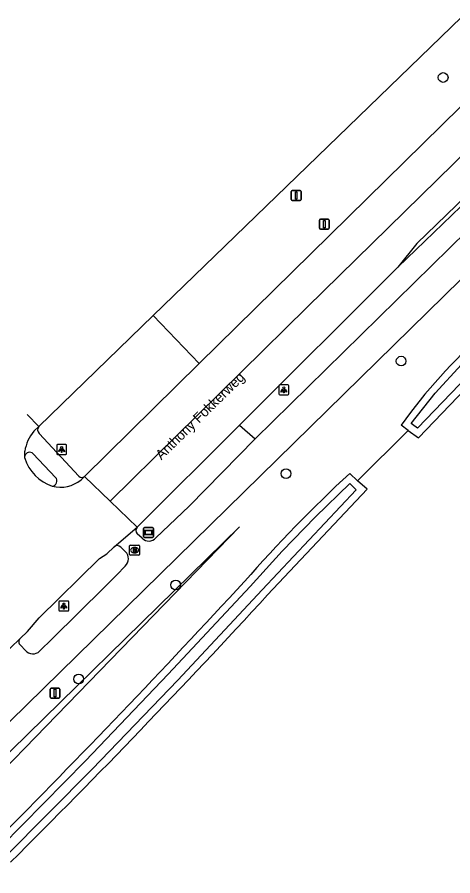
# Model space of a CAD drawing. Extents: x 156502 to 159074, y 384229 to 386094.
# Drawn here: x 156893 to 156936.7, y 385875.5 to 385961.8 of the extents above; entities that cross this region are included whole.
import ezdxf

# ---------------------------------------------------------------- set-up
doc = ezdxf.new("R2010")
doc.units = 0
for name, color, linetype in [('IMGEO_Berm_groen', 7, 'Continuous'), ('IMGEO_Boom', 7, 'Continuous'), ('IMGEO_Brandkraan', 7, 'Continuous'), ('IMGEO_Duiker', 7, 'Continuous'), ('IMGEO_Fietspad_gesloten', 7, 'Continuous'), ('IMGEO_Fietspad_open', 7, 'Continuous'), ('IMGEO_Lichtpunt', 7, 'Continuous'), ('IMGEO_Loofbos', 7, 'Continuous'), ('IMGEO_Openbare_ruimte_label', 7, 'Continuous'), ('IMGEO_OVBaan_gesloten', 7, 'Continuous'), ('IMGEO_Rijbaan_regionaal_gesloten', 7, 'Continuous'), ('IMGEO_Verkeersbordpaal', 7, 'Continuous'), ('IMGEO_Verkeerseiland_open', 7, 'Continuous'), ('IMGEO_Verklikker', 7, 'Continuous'), ('IMGEO_Waterloop', 7, 'Continuous')]:
    doc.layers.add(name, color=color, linetype=linetype)

msp = doc.modelspace()

# ---------------------------------------------------------------- linework, layer by layer
at = {"layer": 'IMGEO_Berm_groen'}
msp.add_lwpolyline([(156915.286, 385920.806), (156916.861, 385919.427)], dxfattribs=at)
at = {"layer": 'IMGEO_Boom'}
for centre in [(156935.717, 385955.717), (156931.498, 385927.235), (156919.949, 385915.936), (156908.883, 385904.761), (156899.148, 385895.304)]:
    msp.add_circle(centre, 0.489, dxfattribs=at)
at = {"layer": 'IMGEO_Brandkraan'}
for p, q in [((156904.254, 385907.821), (156904.254, 385908.673)), ((156904.329, 385908.747), (156905.181, 385908.747)), ((156904.742, 385908.527), (156904.767, 385908.527)), ((156905.255, 385908.673), (156905.255, 385907.821)), ((156905.181, 385907.747), (156904.329, 385907.747)), ((156904.765, 385907.967), (156904.74, 385907.967))]:
    msp.add_line(p, q, dxfattribs=at)
for points in [[(156904.254, 385907.821), (156904.254, 385908.673)], [(156904.329, 385908.747), (156905.181, 385908.747)], [(156904.602, 385908.447), (156904.602, 385908.047), (156904.815, 385908.047)], [(156904.833, 385908.447), (156904.602, 385908.447)], [(156904.781, 385908.366), (156904.727, 385908.366), (156904.727, 385908.29)], [(156905.255, 385908.673), (156905.255, 385907.821)], [(156905.181, 385907.747), (156904.329, 385907.747)], [(156904.727, 385908.29), (156904.78, 385908.29)], [(156904.789, 385908.214), (156904.727, 385908.214), (156904.727, 385908.133)], [(156904.727, 385908.133), (156904.789, 385908.133)]]:
    msp.add_lwpolyline(points, dxfattribs=at)
for centre, radius, start, end in [((156904.331, 385908.671), 0.0765, 91.55205, 178.44795), ((156904.331, 385908.671), 0.0765, 91.55205, 178.44795), ((156904.782, 385908.328), 0.0379, 267.82845, 90.93552), ((156904.837, 385908.302), 0.145, 59.4692, 91.53667), ((156904.862, 385908.349), 0.0922, 285.51372, 58.15012), ((156905.179, 385908.671), 0.0765, 1.55205, 88.44795), ((156905.179, 385908.671), 0.0765, 1.55205, 88.44795), ((156904.331, 385907.823), 0.0765, 181.55205, 268.44795), ((156904.331, 385907.823), 0.0765, 181.55205, 268.44795), ((156904.79, 385908.173), 0.0404, 269.87594, 90.50774), ((156904.821, 385908.298), 0.251, 268.66757, 293.53466), ((156904.867, 385908.157), 0.105, 301.31148, 78.98903), ((156905.179, 385907.823), 0.0765, 271.55205, 358.44795), ((156905.179, 385907.823), 0.0765, 271.55205, 358.44795)]:
    msp.add_arc(centre, radius, start, end, dxfattribs=at)
for centre, major_axis, ratio, start_param, end_param in [((156904.741, 385908.247), (-0.387, 0.002), 0.722429, 4.712389, 7.853982), ((156904.766, 385908.247), (-0.39, 0.002), 0.717154, 1.570796, 4.712389)]:
    msp.add_ellipse(centre, major_axis=major_axis, ratio=ratio, start_param=start_param, end_param=end_param, dxfattribs=at)
at = {"layer": 'IMGEO_Duiker'}
msp.add_lwpolyline([(156932.218, 385920.282), (156927.135, 385915.226)], dxfattribs=at)
at = {"layer": 'IMGEO_Fietspad_gesloten'}
for points in [[(156916.861, 385919.427), (156943.436, 385945.532), (156945.978, 385947.733)], [(156947.572, 385944.991), (156944.187, 385942.001), (156873.791, 385872.985)], [(156916.861, 385919.427), (156910.242, 385912.682), (156906.88, 385909.479)], [(156905.515, 385909.453), (156905.007, 385909.901)], [(156903.357, 385908.566), (156903.843, 385908.097)], [(156903.815, 385906.653), (156902.968, 385905.759), (156901.719, 385904.522), (156896.499, 385899.38), (156895.214, 385898.109)], [(156893.799, 385898.18), (156893.291, 385898.71)]]:
    msp.add_lwpolyline(points, dxfattribs=at)
for centre, radius, start, end in [((156905.345, 385910.229), 0.471, 135.50454, 224.14716), ((156906.186, 385910.074), 0.914, 222.79377, 319.38866), ((156903.002, 385908.185), 0.52, 47.025, 127.15622), ((156903.124, 385907.389), 1.01, 313.22156, 44.55672), ((156893.595, 385899.063), 0.466, 137.59497, 229.26886), ((156894.541, 385898.827), 0.984, 221.09933, 313.15567)]:
    msp.add_arc(centre, radius, start, end, dxfattribs=at)
at = {"layer": 'IMGEO_Fietspad_open'}
for points in [[(156895.173, 385919.975), (156899.156, 385915.676)], [(156896.811, 385915.552), (156894.565, 385917.933)]]:
    msp.add_lwpolyline(points, dxfattribs=at)
for centre, radius, start, end in [((156895.54, 385920.341), 0.518, 140.62707, 224.97438), ((156894.211, 385917.598), 0.488, 43.46439, 167.98882), ((156896.43, 385915.191), 0.525, 276.70868, 43.40858), ((156899.453, 385916.007), 0.445, 228.11208, 305.05783)]:
    msp.add_arc(centre, radius, start, end, dxfattribs=at)
at = {"layer": 'IMGEO_Lichtpunt'}
for p, q in [((156919.223, 385924.747), (156919.223, 385923.94)), ((156919.223, 385924.747), (156919.223, 385923.94)), ((156920.125, 385924.842), (156919.317, 385924.842)), ((156920.125, 385924.842), (156919.317, 385924.842)), ((156920.219, 385923.94), (156920.219, 385924.747)), ((156920.219, 385923.94), (156920.219, 385924.747)), ((156919.317, 385923.846), (156920.125, 385923.846)), ((156919.317, 385923.846), (156920.125, 385923.846)), ((156896.931, 385918.768), (156896.931, 385917.961)), ((156896.931, 385918.768), (156896.931, 385917.961)), ((156897.833, 385918.863), (156897.025, 385918.863)), ((156897.833, 385918.863), (156897.025, 385918.863)), ((156897.927, 385917.961), (156897.927, 385918.768)), ((156897.927, 385917.961), (156897.927, 385918.768)), ((156897.025, 385917.867), (156897.833, 385917.867)), ((156897.025, 385917.867), (156897.833, 385917.867)), ((156898.052, 385903.14), (156897.244, 385903.14)), ((156898.052, 385903.14), (156897.244, 385903.14)), ((156897.15, 385903.045), (156897.15, 385902.238)), ((156897.15, 385903.045), (156897.15, 385902.238)), ((156898.146, 385902.238), (156898.146, 385903.045)), ((156898.146, 385902.238), (156898.146, 385903.045)), ((156897.244, 385902.144), (156898.052, 385902.144)), ((156897.244, 385902.144), (156898.052, 385902.144))]:
    msp.add_line(p, q, dxfattribs=at)
for points in [[(156919.597, 385924.411), (156919.636, 385924.383), (156919.448, 385924.121), (156919.41, 385924.148), (156919.597, 385924.411)], [(156919.699, 385924.363), (156919.746, 385924.363), (156919.746, 385924.041), (156919.699, 385924.041), (156919.699, 385924.363)], [(156919.809, 385924.383), (156919.847, 385924.41), (156920.034, 385924.148), (156919.995, 385924.12), (156919.809, 385924.383)], [(156897.305, 385918.432), (156897.344, 385918.404), (156897.156, 385918.142), (156897.118, 385918.169), (156897.305, 385918.432)], [(156897.407, 385918.384), (156897.454, 385918.384), (156897.454, 385918.062), (156897.407, 385918.062), (156897.407, 385918.384)], [(156897.517, 385918.404), (156897.555, 385918.431), (156897.742, 385918.169), (156897.703, 385918.141), (156897.517, 385918.404)], [(156897.524, 385902.709), (156897.563, 385902.681), (156897.375, 385902.419), (156897.337, 385902.446), (156897.524, 385902.709)], [(156897.626, 385902.661), (156897.673, 385902.661), (156897.673, 385902.339), (156897.626, 385902.339), (156897.626, 385902.661)], [(156897.736, 385902.681), (156897.774, 385902.708), (156897.961, 385902.446), (156897.922, 385902.418), (156897.736, 385902.681)]]:
    msp.add_lwpolyline(points, dxfattribs=at)
for centre in [(156919.722, 385924.545), (156897.43, 385918.566), (156897.649, 385902.843)]:
    msp.add_circle(centre, 0.0994, dxfattribs=at)
for centre, start, end in [((156919.317, 385924.747), 90, 180), ((156919.317, 385924.747), 90, 180), ((156920.125, 385924.747), 0, 90), ((156920.125, 385924.747), 0, 90), ((156919.317, 385923.94), 180, 270), ((156919.317, 385923.94), 180, 270), ((156920.125, 385923.94), 270, 0), ((156920.125, 385923.94), 270, 360), ((156897.025, 385918.768), 90, 180), ((156897.025, 385918.768), 90, 180), ((156897.833, 385918.768), 0, 90), ((156897.833, 385918.768), 0, 90), ((156897.025, 385917.961), 180, 270), ((156897.025, 385917.961), 180, 270), ((156897.833, 385917.961), 270, 0), ((156897.833, 385917.961), 270, 360), ((156897.244, 385903.045), 90, 180), ((156897.244, 385903.045), 90, 180), ((156898.052, 385903.045), 0, 90), ((156898.052, 385903.045), 0, 90), ((156897.244, 385902.238), 180, 270), ((156897.244, 385902.238), 180, 270), ((156898.052, 385902.238), 270, 0), ((156898.052, 385902.238), 270, 360)]:
    msp.add_arc(centre, 0.0946, start, end, dxfattribs=at)
at = {"layer": 'IMGEO_Loofbos'}
for points in [[(156932.218, 385920.282), (156933.24, 385919.544), (156939.53, 385926.107), (156945.972, 385932.521), (156952.047, 385938.123)], [(156932.218, 385920.282), (156931.498, 385920.803)], [(156927.135, 385915.226), (156932.218, 385920.282)], [(156918.102, 385903.758), (156928.076, 385914.361), (156927.135, 385915.226)], [(156926.339, 385915.957), (156927.135, 385915.226)], [(156885.077, 385880.811), (156887.455, 385883.327), (156915.271, 385910.594), (156871.07, 385864.986), (156845.546, 385840.494)]]:
    msp.add_lwpolyline(points, dxfattribs=at)
for centre, radius, start, end in [((156975.945, 385889.003), 54.652, 131.2582, 144.41783), ((157023.66, 385810.802), 143.279, 132.78404, 138.84683), ((156213.51, 386552.027), 954.833, 315.185311, 317.348363), ((156324.09, 386449.06), 806.353, 314.801867, 317.448151)]:
    msp.add_arc(centre, radius, start, end, dxfattribs=at)
at = {"layer": 'IMGEO_OVBaan_gesloten'}
for points in [[(156944.958, 385950.544), (156933.089, 385939.03), (156931.18, 385936.654)], [(156931.18, 385936.654), (156941.12, 385946.235), (156944.931, 385949.532), (156945.978, 385947.733)]]:
    msp.add_lwpolyline(points, dxfattribs=at)
at = {"layer": 'IMGEO_Rijbaan_regionaal_gesloten'}
for points in [[(156906.616, 385931.802), (156937.548, 385961.776)], [(156941.217, 385956.463), (156911.246, 385926.983)], [(156943.271, 385953.427), (156922.067, 385932.665), (156902.29, 385913.167)], [(156915.286, 385920.806), (156931.18, 385936.654)], [(156895.139, 385920.67), (156906.616, 385931.802)], [(156911.246, 385926.983), (156899.709, 385915.643)], [(156895.139, 385920.67), (156893.955, 385921.876)], [(156894.641, 385920.187), (156895.139, 385920.67)], [(156905.009, 385910.559), (156915.286, 385920.806)], [(156893.734, 385917.699), (156893.736, 385918.196)], [(156893.733, 385917.499), (156893.734, 385917.699)], [(156899.709, 385915.643), (156899.374, 385915.313)], [(156902.29, 385913.167), (156899.709, 385915.643)], [(156905.009, 385910.559), (156902.29, 385913.167)], [(156902.688, 385908.6), (156905.009, 385910.559)], [(156893.251, 385899.377), (156894.006, 385900.067), (156895.189, 385901.448), (156901.217, 385907.408), (156901.965, 385907.883), (156902.688, 385908.6)], [(156891.327, 385897.504), (156893.251, 385899.377)]]:
    msp.add_lwpolyline(points, dxfattribs=at)
for centre, radius, start, end in [((156897.567, 385917.656), 3.869, 139.13924, 171.97285), ((156897.884, 385918.787), 4.346, 197.23936, 251.30448), ((156897.286, 385917.892), 3.318, 256.14285, 309.00313)]:
    msp.add_arc(centre, radius, start, end, dxfattribs=at)
at = {"layer": 'IMGEO_Verkeersbordpaal'}
for p, q in [((156920.478, 385943.475), (156920.478, 385944.275)), ((156920.478, 385944.275), (156920.478, 385943.475)), ((156920.578, 385944.375), (156921.368, 385944.375)), ((156921.368, 385944.375), (156920.578, 385944.375)), ((156921.468, 385944.275), (156921.468, 385943.475)), ((156921.468, 385943.475), (156921.468, 385944.275)), ((156921.368, 385943.375), (156920.578, 385943.375)), ((156920.578, 385943.375), (156921.368, 385943.375)), ((156923.293, 385940.579), (156923.293, 385941.379)), ((156923.293, 385941.379), (156923.293, 385940.579)), ((156923.393, 385941.479), (156924.183, 385941.479)), ((156924.183, 385941.479), (156923.393, 385941.479)), ((156924.283, 385941.379), (156924.283, 385940.579)), ((156924.283, 385940.579), (156924.283, 385941.379)), ((156924.183, 385940.479), (156923.393, 385940.479)), ((156923.393, 385940.479), (156924.183, 385940.479)), ((156896.266, 385893.5), (156896.266, 385894.3)), ((156896.266, 385894.3), (156896.266, 385893.5)), ((156896.366, 385894.4), (156897.156, 385894.4)), ((156897.156, 385894.4), (156896.366, 385894.4)), ((156897.256, 385894.3), (156897.256, 385893.5)), ((156897.256, 385893.5), (156897.256, 385894.3)), ((156897.156, 385893.4), (156896.366, 385893.4)), ((156896.366, 385893.4), (156897.156, 385893.4))]:
    msp.add_line(p, q, dxfattribs=at)
for points in [[(156920.898, 385944.25), (156921.048, 385944.25), (156921.048, 385943.5), (156920.898, 385943.5), (156920.898, 385944.25)], [(156923.713, 385941.354), (156923.863, 385941.354), (156923.863, 385940.604), (156923.713, 385940.604), (156923.713, 385941.354)], [(156896.686, 385894.275), (156896.836, 385894.275), (156896.836, 385893.525), (156896.686, 385893.525), (156896.686, 385894.275)]]:
    msp.add_lwpolyline(points, dxfattribs=at)
for centre, start, end in [((156920.578, 385944.275), 90, 180), ((156920.578, 385944.275), 90, 180), ((156921.368, 385944.275), 0, 90), ((156921.368, 385944.275), 360, 90), ((156920.578, 385943.475), 180, 270), ((156920.578, 385943.475), 180, 270), ((156921.368, 385943.475), 270, 0), ((156921.368, 385943.475), 270, 0), ((156923.393, 385941.379), 90, 180), ((156923.393, 385941.379), 90, 180), ((156924.183, 385941.379), 0, 90), ((156924.183, 385941.379), 360, 90), ((156923.393, 385940.579), 180, 270), ((156923.393, 385940.579), 180, 270), ((156924.183, 385940.579), 270, 0), ((156924.183, 385940.579), 270, 0), ((156896.366, 385894.3), 90, 180), ((156896.366, 385894.3), 90, 180), ((156897.156, 385894.3), 0, 90), ((156897.156, 385894.3), 360, 90), ((156896.366, 385893.5), 180, 270), ((156896.366, 385893.5), 180, 270), ((156897.156, 385893.5), 270, 0), ((156897.156, 385893.5), 270, 0)]:
    msp.add_arc(centre, 0.1, start, end, dxfattribs=at)
at = {"layer": 'IMGEO_Verkeerseiland_open'}
msp.add_lwpolyline([(156911.246, 385926.983), (156906.616, 385931.802)], dxfattribs=at)
at = {"layer": 'IMGEO_Verklikker'}
for p, q in [((156905.653, 385909.637), (156905.653, 385910.437)), ((156905.653, 385910.437), (156905.653, 385909.637)), ((156905.753, 385910.537), (156906.543, 385910.537)), ((156906.543, 385910.537), (156905.753, 385910.537)), ((156906.643, 385910.437), (156906.643, 385909.637)), ((156906.643, 385909.637), (156906.643, 385910.437)), ((156906.543, 385909.537), (156905.753, 385909.537)), ((156905.753, 385909.537), (156906.543, 385909.537))]:
    msp.add_line(p, q, dxfattribs=at)
for points in [[(156905.754, 385910.269), (156906.542, 385910.269), (156906.542, 385909.805), (156905.754, 385909.805), (156905.754, 385910.269)], [(156905.819, 385910.204), (156905.819, 385909.87), (156906.477, 385909.87), (156906.477, 385910.204), (156905.819, 385910.204)]]:
    msp.add_lwpolyline(points, dxfattribs=at)
for centre, start, end in [((156905.753, 385910.437), 90, 180), ((156905.753, 385910.437), 90, 180), ((156906.543, 385910.437), 0, 90), ((156906.543, 385910.437), 360, 90), ((156905.753, 385909.637), 180, 270), ((156905.753, 385909.637), 180, 270), ((156906.543, 385909.637), 270, 0), ((156906.543, 385909.637), 270, 0)]:
    msp.add_arc(centre, 0.1, start, end, dxfattribs=at)
at = {"layer": 'IMGEO_Waterloop'}
for points in [[(156951.435, 385939.137), (156945.474, 385933.04), (156939.017, 385926.611), (156933.154, 385920.493), (156932.639, 385920.865), (156932.503, 385920.963), (156934.923, 385924.016), (156937.558, 385926.886), (156940.393, 385929.559), (156951.123, 385939.652)], [(156917.548, 385904.272), (156927.002, 385914.322), (156926.624, 385914.669), (156926.342, 385914.928), (156922.893, 385911.593), (156919.557, 385908.145), (156916.339, 385904.585), (156908.134, 385895.789), (156899.818, 385887.098), (156891.394, 385878.511)], [(156891.761, 385877.452), (156900.494, 385886.259), (156909.091, 385895.2), (156917.548, 385904.272)]]:
    msp.add_lwpolyline(points, dxfattribs=at)

# ---------------------------------------------------------------- texts
at = {"layer": 'IMGEO_Openbare_ruimte_label'}
msp.add_text('Anthony Fokkerweg', height=1, rotation=44.3517, dxfattribs=at).set_placement((156907.437, 385917.256))

doc.saveas('drawing.dxf')
